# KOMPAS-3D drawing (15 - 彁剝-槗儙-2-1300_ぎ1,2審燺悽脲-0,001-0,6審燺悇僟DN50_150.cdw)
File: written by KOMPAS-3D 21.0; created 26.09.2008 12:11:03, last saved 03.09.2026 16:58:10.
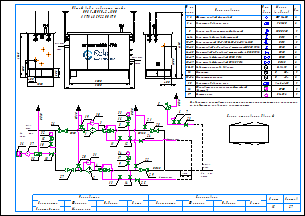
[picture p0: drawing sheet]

Sheets 1-2: A3, landscape

Document properties: Наименование: Макро:21; Автор: RaskoAdmin; Форматы листов документа: 2xA3; Полное имя файла: \\UR38nt01\Departments\КТО\КБ ПУРДГ\Заявки\Прайс-лист на типовые шкафы ГРПШ\ПРДГ_стандарт_20_03_2026\ПРДГ с РДГ(Н, В)\ПРДГ-ШУГО-2-1300_до1,2МПа_Рвых-0,001-0,6МПа_РДГ_DN50_150.cdw

Title block, sheet 1: Наименование: Пункт учета газа / ПУГ-Ш-400-Р / ЛГТИ.485922.001ТУ; designation: ЛГТИ.03.4411141; sheet number: 1; Количество листов документа: 2; organisation: ООО "ЭЛЬСТЕР Газэлектроника"; Форматы листов документа: A3; stored path: C:\Рабочие документы\Компас\ПУГ\Схема.cdw; Разработал: Устинов; Проверил: Кошкин; Утвердил: Кошкин
Title block, sheet 2: sheet number: 2; stored path: D:\Рабочие документы\Заявки\ПУРДГ\ПУРДГ-ШУЭО-2-100-Р 4411220.cdw; designation, second copy: ЛГТИ.03.4411141-

Views: Вид 1, Вид 2
Referenced files: wcvoit.frw
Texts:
  Normal
  Общий вид и габариты шкафа
  ПРДГ-ШУГО-2-1300
  Вход
  газа
  PDI
  Выход
  Р=     кПа
  DN125
  DN50
  DN20
  Импульс DN20
  ≥5DN
  HYSWLongFangSong
  Р=       МПа
  № на
  схеме
  Усл.
  обозн.
  Марка
  (модель)
  Кол.
  Фильтр газовый фланцевый
  ФГ 16-50
  Регулятор давления газа
  РДГ-50
  Клапан предохранительный сбросной
  КПС DN20
  Кран шаровой газовый латунный
  DN15
  Кран кнопочный VE-РАСКО-НЗ-1,6-G1/2-М20
  Кран шаровой "под приварку" штуцерный DN20 PN16
  Кран шаровой "под приварку" штуцерный п/п DN20 PN16
  Кран шаровой фланцевый DN50 PN16
  Кран шаровой фланцевый DN125 PN16
  Индикатор перепада давления
  Delta 15
  Манометр
  Манометр-напоромер
  0...     МПа
  0...     кПа
  Обогреватель газогорелочный шкафной
  (Эльтон")
  Счетчик газа
  Venio-A-15
  ОГШН
  BK-G1,6
  Схема открывания дверей
  Предприятие изготовитель может заменять комплектующие на аналогичные,
  не ухудшающие заявленных характеристик.
  Вход газа
  Выход газа
  logo-rasko-ge(1).png
  Должность
  Конструктор
  Фамилия
  Подпись
  Дата
  Согласовано
  Максимкин
  Лист
  Листов
  POLYLINE_STYLE_0.18_RGB_0_0_0
  POLYLINE_STYLE_0.50_RGB_0_0_0
  POLYLINE_STYLE_0.34_RGB_0_0_0
  PHANTOM_RGB_0_0_0_SC_1_THICK_0.18
  K5LT_THIN_RGB_0_0_0_THICK_0.18
  K5LT32769_RGB_0_0_0_THICK_0.18
  K5LT12_RGB_0_0_0_SC_1_THICK_0.18
  K5LT_DASHED_RGB_0_0_0_SC_1_THICK_0.18
  ACISOTGL_RGB_0_0_0_SC_0.8_THICK_0.25
  CONTINUOUS_RGB_0_127_31_THICK_0.3
  CONTINUOUS_RGB_0_0_255_THICK_0.35
  CONTINUOUS_RGB_255_0_0_THICK_0.35
  POLYLINE_STYLE_0.25_RGB_0_0_0
  CONTINUOUS_RGB_0_0_0_THICK_0.5
  POLYLINE_STYLE_0.35_RGB_0_0_255
  CONTINUOUS_RGB_0_0_0_THICK_0.4
  CONTINUOUS_RGB_0_0_0_THICK_0.35
  Без оформления
Dimensions and other numbers on the sheet: 1; 2; 3; 4; 5; 10; 27; 28; 29; 23; 8; 12; 19; 20; 21; 22; 25; 24; 30; 31; 15; 16; 32; 26; 6; 7; 11; 14; 13; 33; 9; 17; 34; 18; 35; 36; 37; 1, 2; 3, 4; 6-14; 15-17; 18-23; 24-25; 26-27; 28-29; 30-31; 33-34; 400; 1050; 500; 305; 1565; 1000; 4130; 3000; 3300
